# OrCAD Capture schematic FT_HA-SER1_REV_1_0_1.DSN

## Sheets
1 INDEX: title: INDEX; rev: 1.0; note: 17 HaYetsira Street; note: Yokneam Illit, Israel 2069208
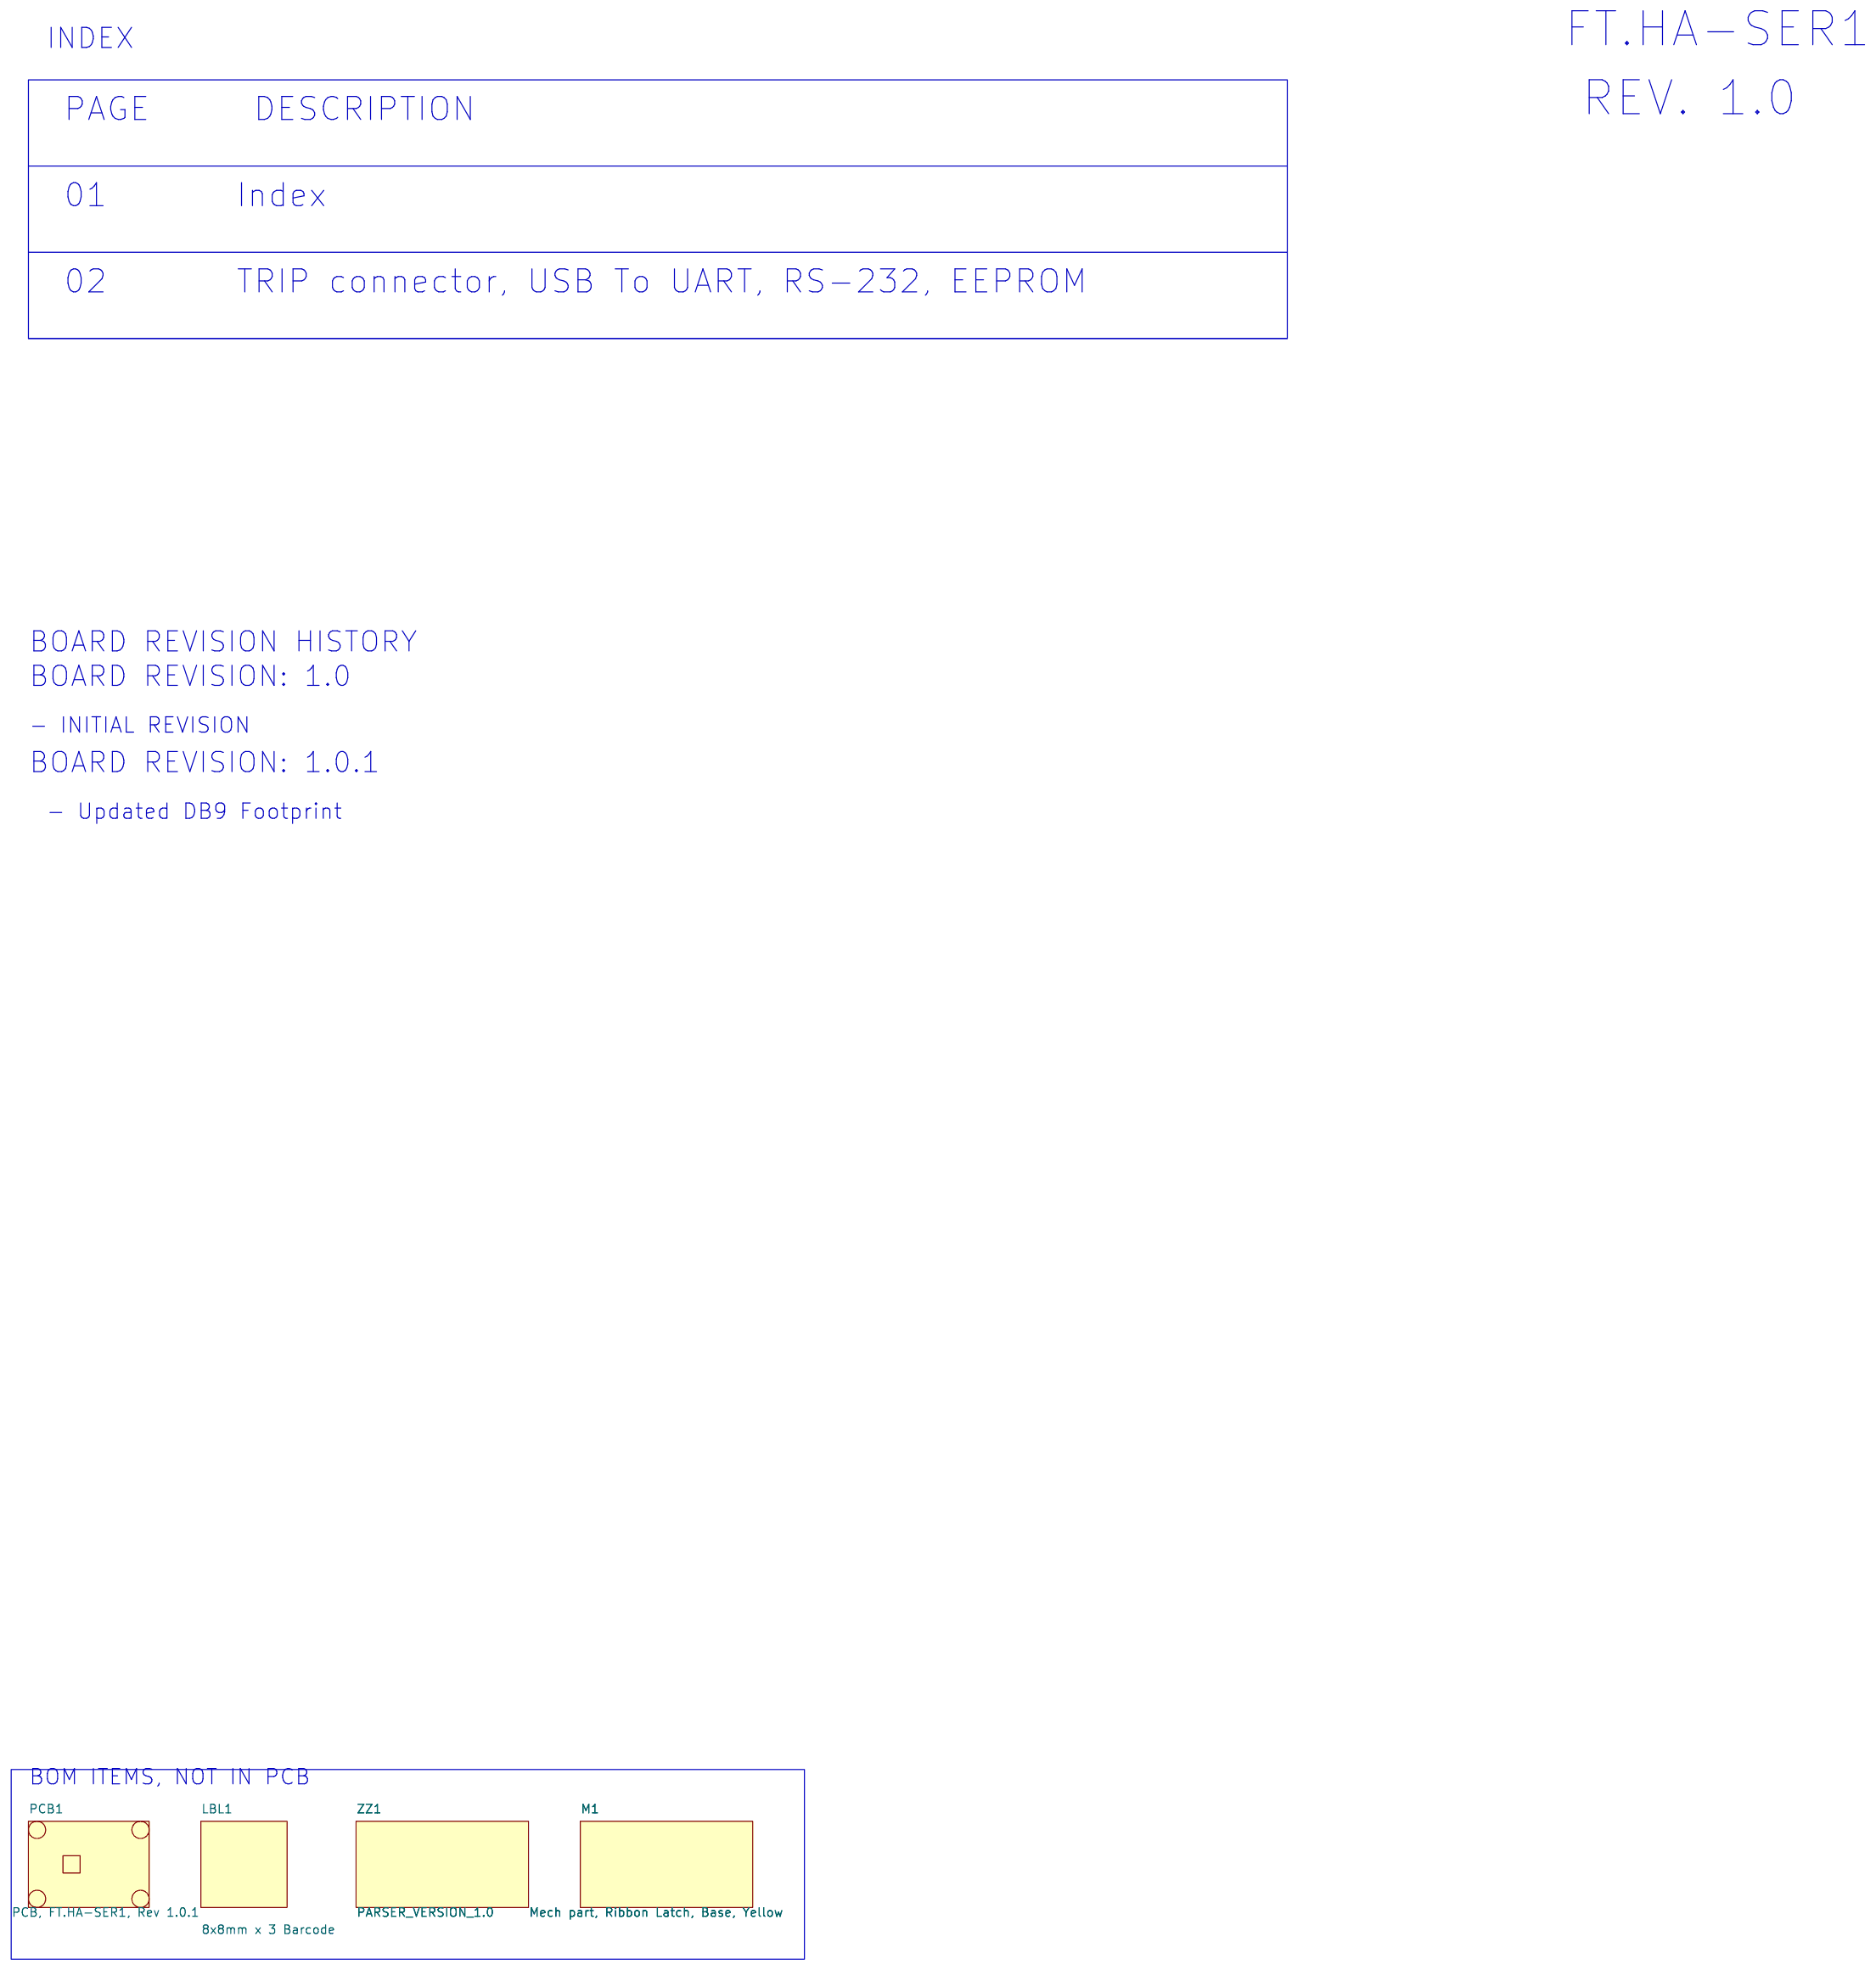
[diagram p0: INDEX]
2 TRIP + USB2UART: size A3; title: 02-TRIP + USB2UART
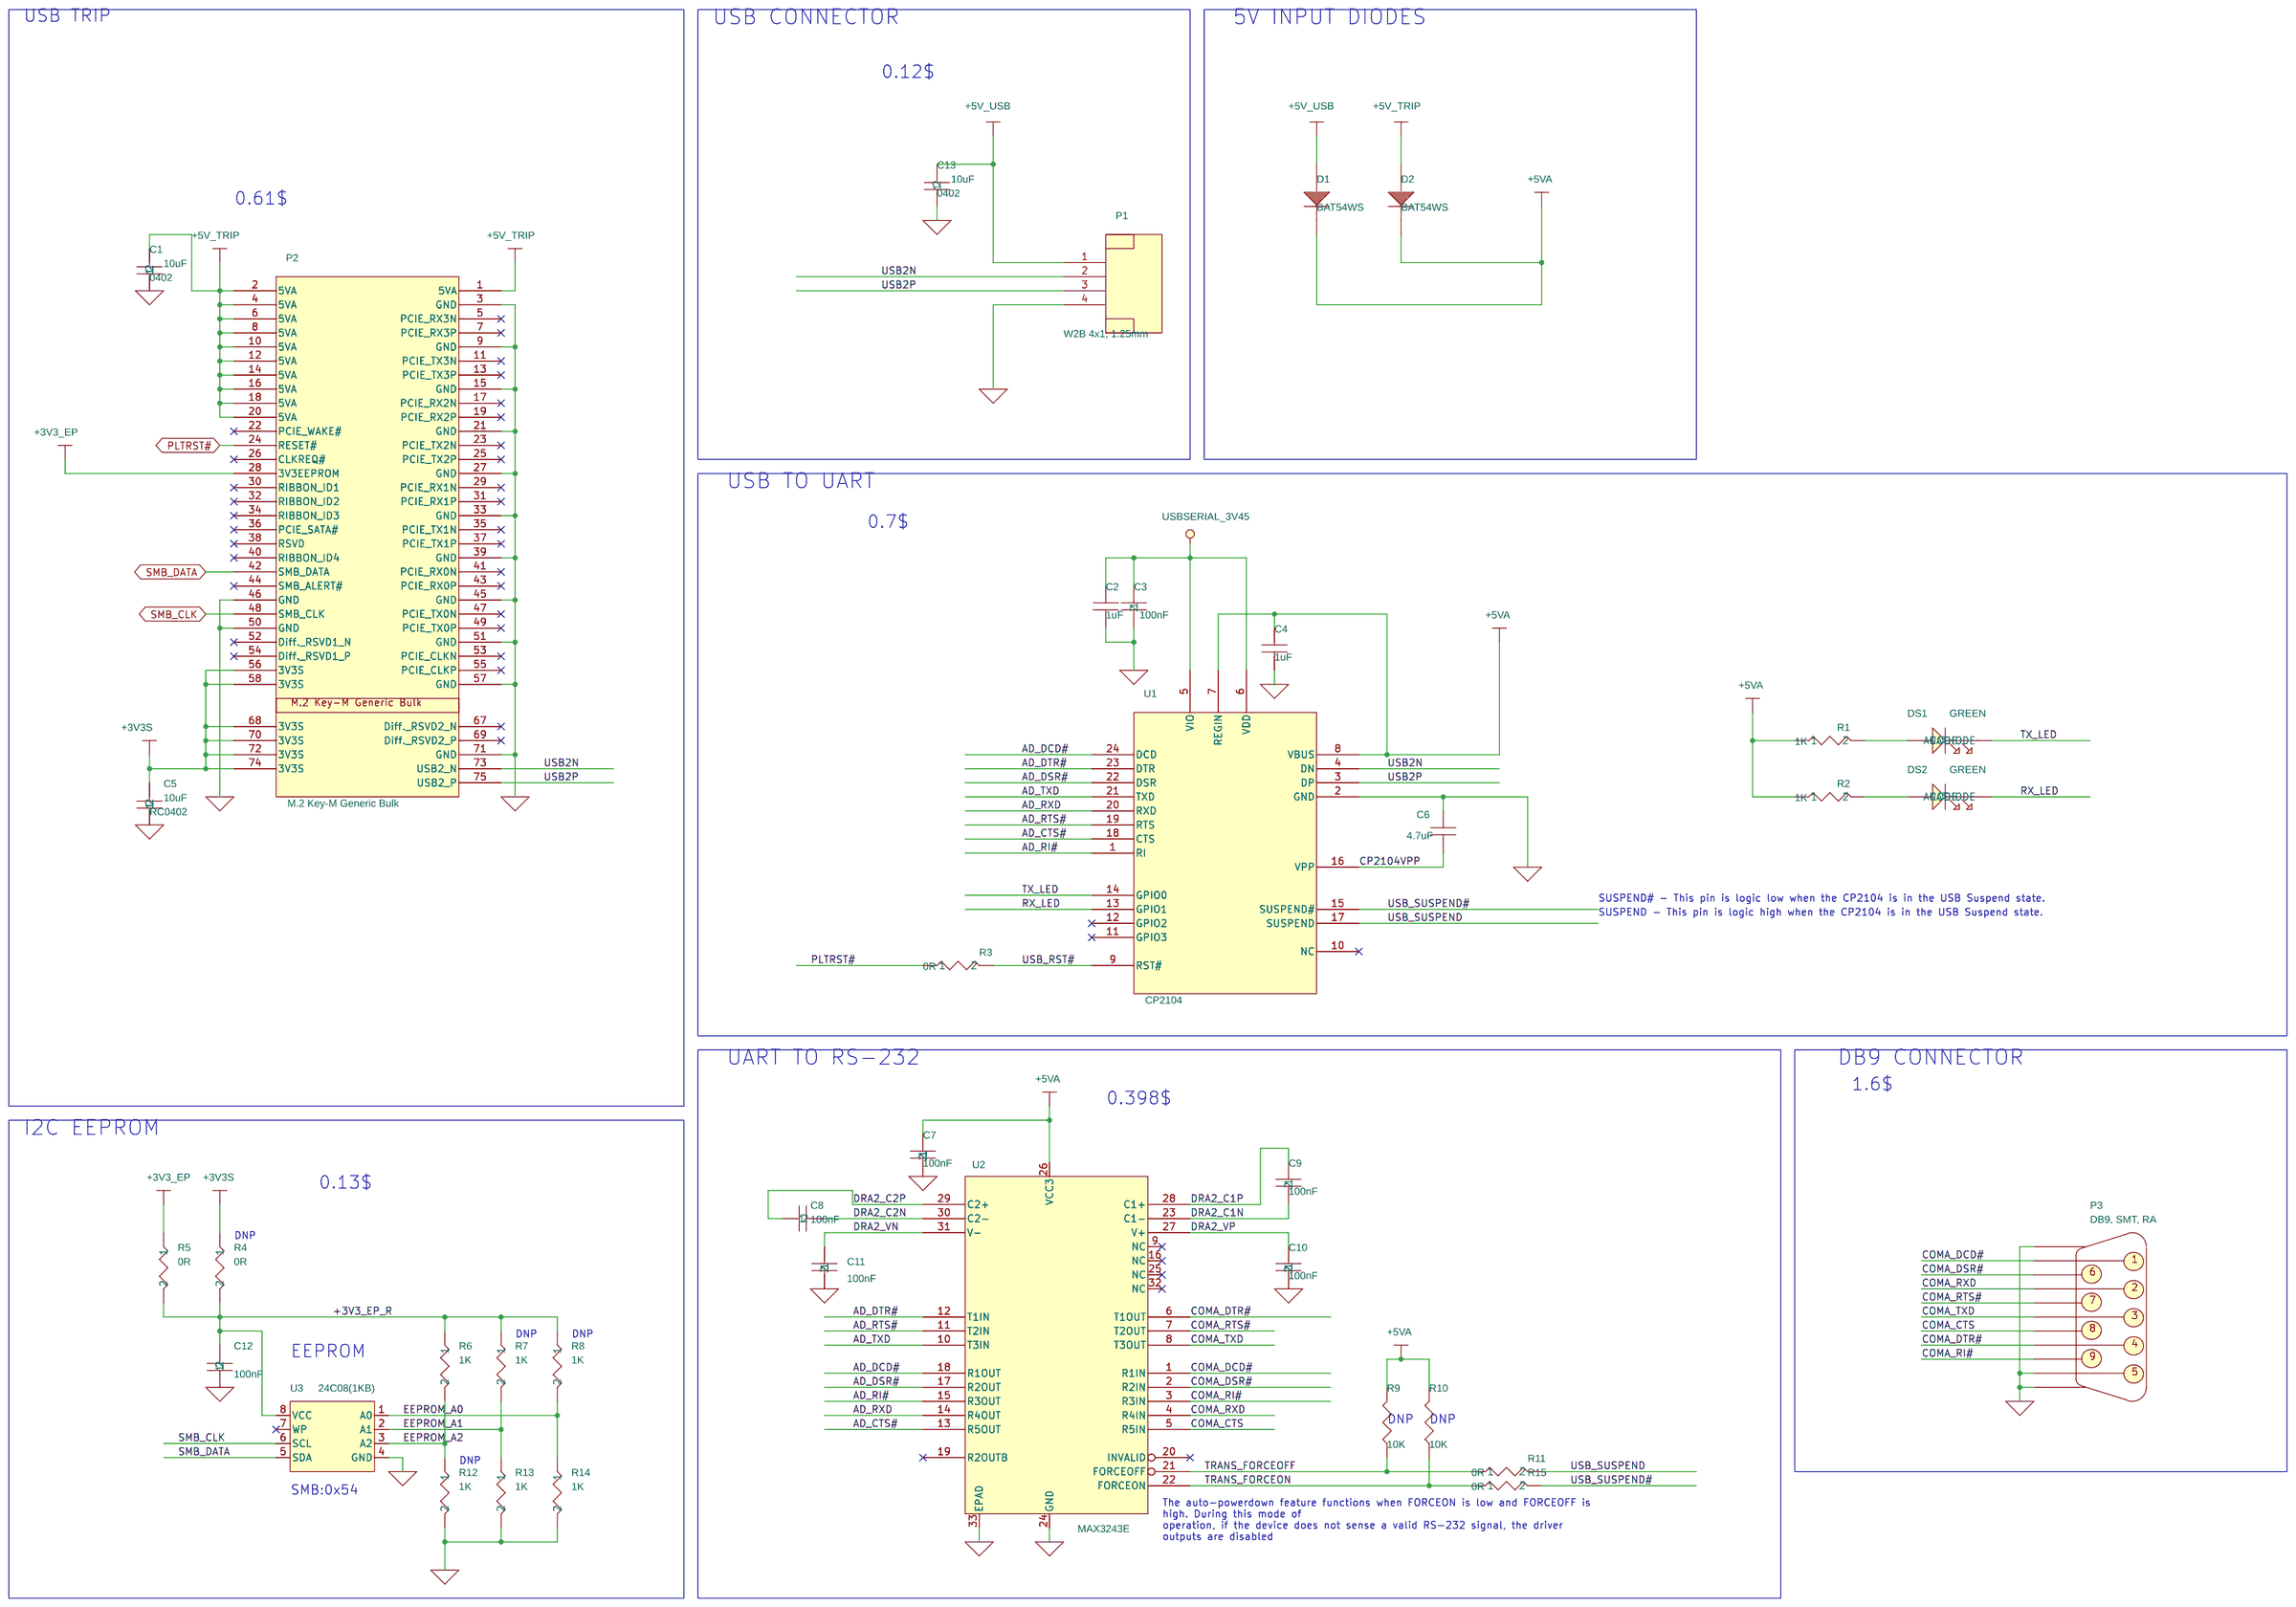
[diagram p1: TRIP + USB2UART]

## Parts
sheet INDEX
LBL1  8x8mm x 3 Barcode  [LBL XYU]
M1  Mech part, Ribbon Latch, Base, Yellow
PCB1  PCB, FT.HA-SER1, Rev 1.0.1
ZZ1  PARSER_VERSION_1.0
sheet TRIP + USB2UART
C1  10uF  [0402]
C2  1uF  [RC0402]
C3  100nF  [RC0402]
C4  1uF  [RC0402]
C5  10uF  [RC0402]
C6  4.7uF  [C0603-08]
C7  100nF  [RC0402]
C8  100nF  [RC0402]
C9  100nF  [RC0402]
C10  100nF  [RC0402]
C11  100nF  [RC0402]
C12  100nF  [RC0402]
C13  10uF  [0402]
D1  BAT54WS  [SOD-323]
D2  BAT54WS  [SOD-323]
DS1  GREEN  [LED-0603]
DS2  GREEN  [LED-0603]
P1  W2B 4x1, 1.25mm  [1x4W2B1_25RASM]
P2  M.2 Key-M Generic Bulk  [NGFF67P8HMkeySM]
P3  DB9, SMT, RA
R1  1K  [RC0402]
R2  1K  [RC0402]
R3  0R  [RC0402]
R4  0R  [RC0402]
R5  0R  [RC0402]
R6  1K  [RC0402]
R7  1K  [RC0402]
R8  1K  [RC0402]
R9  10K  [RC0402]
R10  10K  [RC0402]
R11  0R  [RC0402]
R12  1K  [RC0402]
R13  1K  [RC0402]
R14  1K  [RC0402]
R15  0R  [RC0402]
U1  CP2104  [MO-220VGGD-8]
U2  MAX3243E  [QFN5x5-32]
U3  24C08(1KB)  [MO-229VCED-2]

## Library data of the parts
LBL1 = Label_8x8mm_x_3_for_Barcode: CLABCONF0: =SER
M1 = PARSER_VERSION_1_0.0: CLABCONF0: =SER; P/N: 290E010010
PCB1 = SBC-iHSW_Rev_1.0: CLABCONF0: =SER; P/N: 188C03771U
ZZ1 = PARSER_VERSION_1.0: CLABCONF0: =SER
C1 = 100nF,_10V,_X7R,_10%,_0402_3: CLABCONF0: =SER; P/N: 151B10600S
C2 C4 = 1uF,X5R,6.3V,0402: CLABCONF0: =SER
C3 = 100nF,_10V,_X7R,_10%,_0402_1: CLABCONF0: =SER
C5 = 100nF,_10V,_X7R,_10%,_0402_2: CLABCONF0: =SER; P/N: 151B10600S
C6 = 4.7uF,_6.3V,_X5R,_20%,_0603: CLABCONF0: =SER
C7 = 15pF,_50V,_NPO,_5%,_0402_5: CLABCONF0: =SER; P/N: 151B10400S
C8 = 15pF,_50V,_NPO,_5%,_0402_1: CLABCONF0: =SER; P/N: 151B10400S
C9 = 15pF,_50V,_NPO,_5%,_0402_2: CLABCONF0: =SER; P/N: 151B10400S
C10 = 15pF,_50V,_NPO,_5%,_0402_3: CLABCONF0: =SER; P/N: 151B10400S
C11 = 15pF,_50V,_NPO,_5%,_0402_4: CLABCONF0: =SER; P/N: 151B10400S
C12 = 15pF,_50V,_NPO,_5%,_0402: CLABCONF0: =SER; P/N: 151B10400S
C13 = 100nF,_10V,_X7R,_10%,_0402: CLABCONF0: =SER; P/N: 151B10600S
D1 D2 = BAT54WS: CLABCONF0: =SER
DS1 = LED-RED_1206: CLABCONF0: =SER; P/N: 139A10260S
DS2 = LED-RED_1206_1: CLABCONF0: =SER; P/N: 139A10260S
P1 = W2B_4x1_HDR,_1.25mm: CLABCONF0: =SER; P/N: 182E00401S
P2 = M.2_Key-M_Generic_Bulk: CLABCONF0: =SER; P/N: 182K06700S
P3 = DB9,_SMT,_RA: CLABCONF0: =SER; P/N: 180C00901S
R1 = 348R,1%,0402,1_16W_9: CLABCONF0: =SER; P/N: 161C10011S
R2 = 348R,1%,0402,1_16W: CLABCONF0: =SER; P/N: 161C10011S
R3 = 348R,1%,0402,1_16W_4: CLABCONF0: =SER; P/N: 161C00005S
R4 = 348R,1%,0402,1_16W_6: CLABCONF0: =DNP; P/N: 161C00005S
R5 = 348R,1%,0402,1_16W_12: CLABCONF0: =SER; P/N: 161C00005S
R6 = 348R,1%,0402,1_16W_3: CLABCONF0: =SER; P/N: 161C10011S
R7 = 348R,1%,0402,1_16W_8: CLABCONF0: =DNP; P/N: 161C10011S
R8 = 348R,1%,0402,1_16W_7: CLABCONF0: =DNP; P/N: 161C10011S
R9 R10 = 10K,1%,0402,1_16W_0: CLABCONF0: =DNP; Group: Always
R11 = 348R,1%,0402,1_16W_10: CLABCONF0: =SER; P/N: 161C00005S
R12 = 348R,1%,0402,1_16W_5: CLABCONF0: =DNP; P/N: 161C10011S
R13 = 348R,1%,0402,1_16W_1: CLABCONF0: =SER; P/N: 161C10011S
R14 = 348R,1%,0402,1_16W_11: CLABCONF0: =SER; P/N: 161C10011S
R15 = 348R,1%,0402,1_16W_2: CLABCONF0: =SER; P/N: 161C00005S
U1 = CP2104_0: CLABCONF0: =SER; P/N: 116A00140S
U2 = MAX3243E_RS-232_3T5R_BGA: CLABCONF0: =SER
U3 = 24C02,_serial_EE,_2KB,_I2C: CLABCONF0: =SER; P/N: 111S31000S

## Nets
+3V3_EP: P2.28(3V3EEPROM) R5.1
+3V3_EP_R: C12.2 R4.2 R5.2 R6.1 R7.1 R8.1 U3.8(VCC)
+3V3S: C5.2 P2.56(3V3S) P2.58(3V3S) P2.68(3V3S) P2.70(3V3S) P2.72(3V3S) P2.74(3V3S) R4.1
+5V_TRIP: C1.2 D2.ANODE P2.1(5VA) P2.2(5VA) P2.4(5VA) P2.6(5VA) P2.8(5VA) P2.10(5VA) P2.12(5VA) P2.14(5VA) P2.16(5VA) P2.18(5VA) P2.20(5VA)
+5V_USB: C13.2 D1.ANODE P1.1
+5VA: C4.1 C7.1 D1.CATHODE D2.CATHODE R1.1 R2.1 R9.2 R10.2 U1.7(REGIN) U1.8(VBUS) U2.26(VCC3)
GND: C1.1 C2.2 C3.2 C4.2 C5.1 C6.2 C7.2 C10.2 C11.2 C12.1 C13.1 P1.4 P2.3(GND) P2.9(GND) P2.15(GND) P2.21(GND) P2.27(GND) P2.33(GND) P2.39(GND) P2.45(GND) P2.46(GND) P2.50(GND) P2.51(GND) P2.57(GND) P2.71(GND) P3.5 P3.10 P3.11 R12.2 R13.2 R14.2 U1.2(GND) U2.24(GND) U2.33(EPAD) U3.4(GND)
AD_CTS#: U1.18(CTS) U2.13(R5OUT)
AD_DCD#: U1.24(DCD) U2.18(R1OUT)
AD_DSR#: U1.22(DSR) U2.17(R2OUT)
AD_DTR#: U1.23(DTR) U2.12(T1IN)
AD_RI#: U1.1(RI) U2.15(R3OUT)
AD_RTS#: U1.19(RTS) U2.11(T2IN)
AD_RXD: U1.20(RXD) U2.14(R4OUT)
AD_TXD: U1.21(TXD) U2.10(T3IN)
COMA_CTS: P3.8 U2.5(R5IN)
COMA_DCD#: P3.1 U2.1(R1IN)
COMA_DSR#: P3.6 U2.2(R2IN)
COMA_DTR#: P3.4 U2.6(T1OUT)
COMA_RI#: P3.9 U2.3(R3IN)
COMA_RTS#: P3.7 U2.7(T2OUT)
COMA_RXD: P3.2 U2.4(R4IN)
COMA_TXD: P3.3 U2.8(T3OUT)
CP2104VPP: C6.1 U1.16(VPP)
DRA2_C1N: C9.2 U2.23(C1-)
DRA2_C1P: C9.1 U2.28(C1+)
DRA2_C2N: C8.2 U2.30(C2-)
DRA2_C2P: C8.1 U2.29(C2+)
DRA2_VN: C11.1 U2.31(V-)
DRA2_VP: C10.1 U2.27(V+)
EEPROM_A0: R8.2 R14.1 U3.1(A0)
EEPROM_A1: R7.2 R13.1 U3.2(A1)
EEPROM_A2: R6.2 R12.1 U3.3(A2)
PLTRST#: P2.24(RESET#) R3.1
RX_LED: DS2.CATHODE U1.13(GPIO1)
SMB_CLK: P2.48(SMB_CLK) U3.6(SCL)
SMB_DATA: P2.42(SMB_DATA) U3.5(SDA)
TRANS_FORCEOFF: R9.1 R11.1 U2.21(FORCEOFF)
TRANS_FORCEON: R10.1 R15.1 U2.22(FORCEON)
TX_LED: DS1.CATHODE U1.14(GPIO0)
USB2N: P1.2 P2.73(USB2_N) U1.4(DN)
USB2P: P1.3 P2.75(USB2_P) U1.3(DP)
USB_RST#: R3.2 U1.9(RST#)
USB_SUSPEND: R11.2 U1.17(SUSPEND)
USB_SUSPEND#: R15.2 U1.15(SUSPEND#)
USBSERIAL_3V45: C2.1 C3.1 U1.5(VIO) U1.6(VDD)
N16853514: DS1.ANODE R1.2
N16853517: DS2.ANODE R2.2

Not connected (* = marked no-connect by the designer): P2 5(PCIE_RX3N)* 7(PCIE_RX3P)* 11(PCIE_TX3N)* 13(PCIE_TX3P)* 17(PCIE_RX2N)* 19(PCIE_RX2P)* 22(PCIE_WAKE#)* 23(PCIE_TX2N)* 25(PCIE_TX2P)* 26(CLKREQ#)* 29(PCIE_RX1N)* 30(RIBBON_ID1)* 31(PCIE_RX1P)* 32(RIBBON_ID2)* 34(RIBBON_ID3)* 35(PCIE_TX1N)* 36(PCIE_SATA#)* 37(PCIE_TX1P)* 38(RSVD)* 40(RIBBON_ID4)* 41(PCIE_RX0N)* 43(PCIE_RX0P)* 44(SMB_ALERT#)* 47(PCIE_TX0N)* 49(PCIE_TX0P)* 52(Diff._RSVD1_N)* 53(PCIE_CLKN)* 54(Diff._RSVD1_P)* 55(PCIE_CLKP)* 67(Diff._RSVD2_N)* 69(Diff._RSVD2_P)*; U1 10(NC)* 11(GPIO3)* 12(GPIO2)*; U2 9(NC)* 16(NC)* 19(R2OUTB)* 20(INVALID)* 25(NC)* 32(NC)*; U3 7(WP)*

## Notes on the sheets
sheet 1
- FT.HA-SER1
- INDEX
- REV. 1.0
- PAGE
- DESCRIPTION
- 01
- Index
- 02
- TRIP connector, USB To UART, RS-232, EEPROM
- BOARD REVISION HISTORY
- BOARD REVISION: 1.0
- - INITIAL REVISION
- BOARD REVISION: 1.0.1
- - Updated DB9 Footprint
- BOM ITEMS, NOT IN PCB
sheet 2
- USB TRIP
- USB CONNECTOR
- 5V INPUT DIODES
- 0.12$
- 0.61$
- USB TO UART
- 0.7$
- SUSPEND# - This pin is logic low when the CP2104 is in the USB Suspend state.
- SUSPEND - This pin is logic high when the CP2104 is in the USB Suspend state.
- UART TO RS-232
- DB9 CONNECTOR
- 1.6$
- 0.398$
- I2C EEPROM
- 0.13$
- DNP
- DNP
- DNP
- EEPROM
- DNP
- DNP
- DNP
- SMB:0x54
- The auto-powerdown feature functions when FORCEON is low and FORCEOFF is
  high. During this mode of
  operation, if the device does not sense a valid RS-232 signal, the driver
  outputs are disabled
